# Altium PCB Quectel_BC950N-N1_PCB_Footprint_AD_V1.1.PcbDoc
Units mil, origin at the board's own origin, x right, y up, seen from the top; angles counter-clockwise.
Board outline 6000 x 4000 mil, 2 copper layers (Top Layer, Bottom Layer); 1 components, 0 nets, 94 pads, 0 vias.
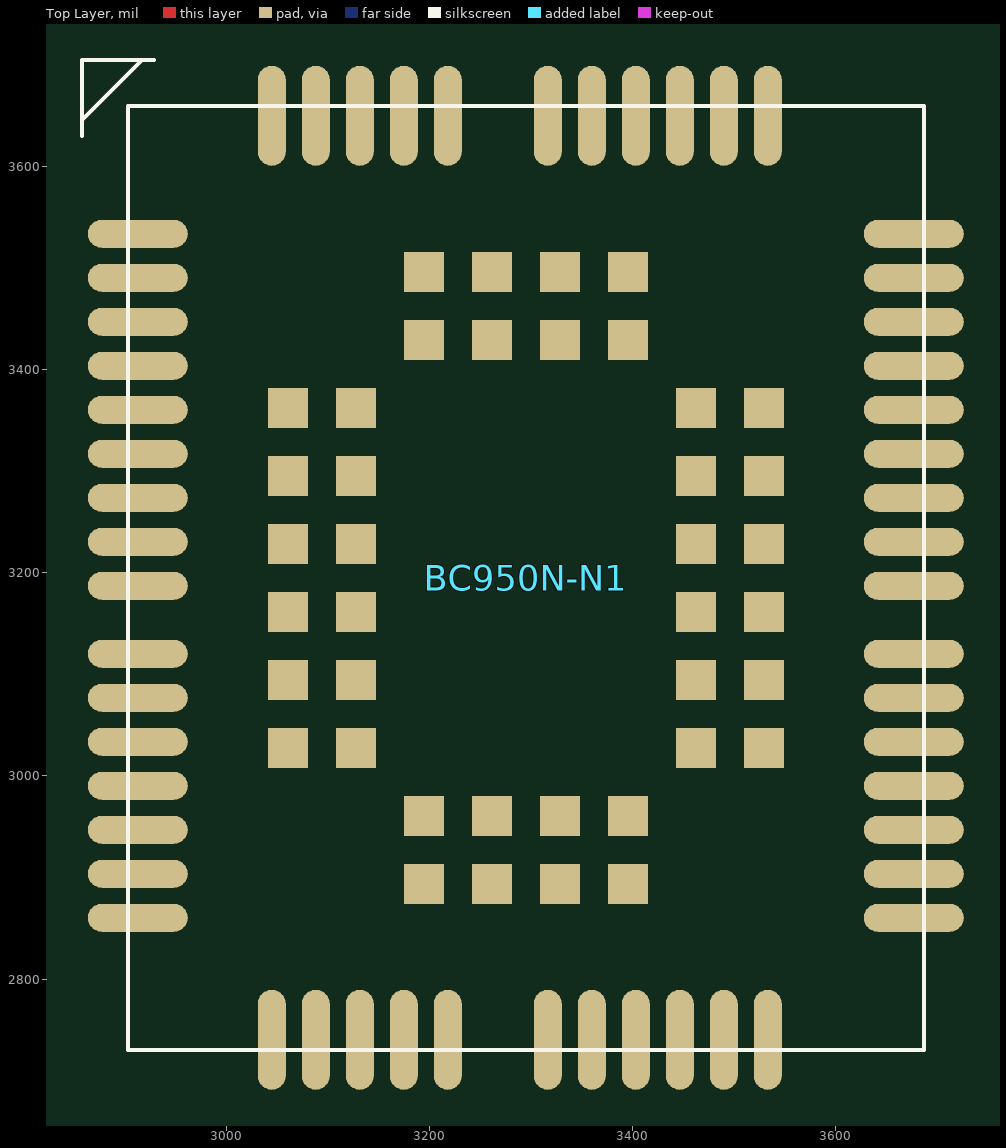
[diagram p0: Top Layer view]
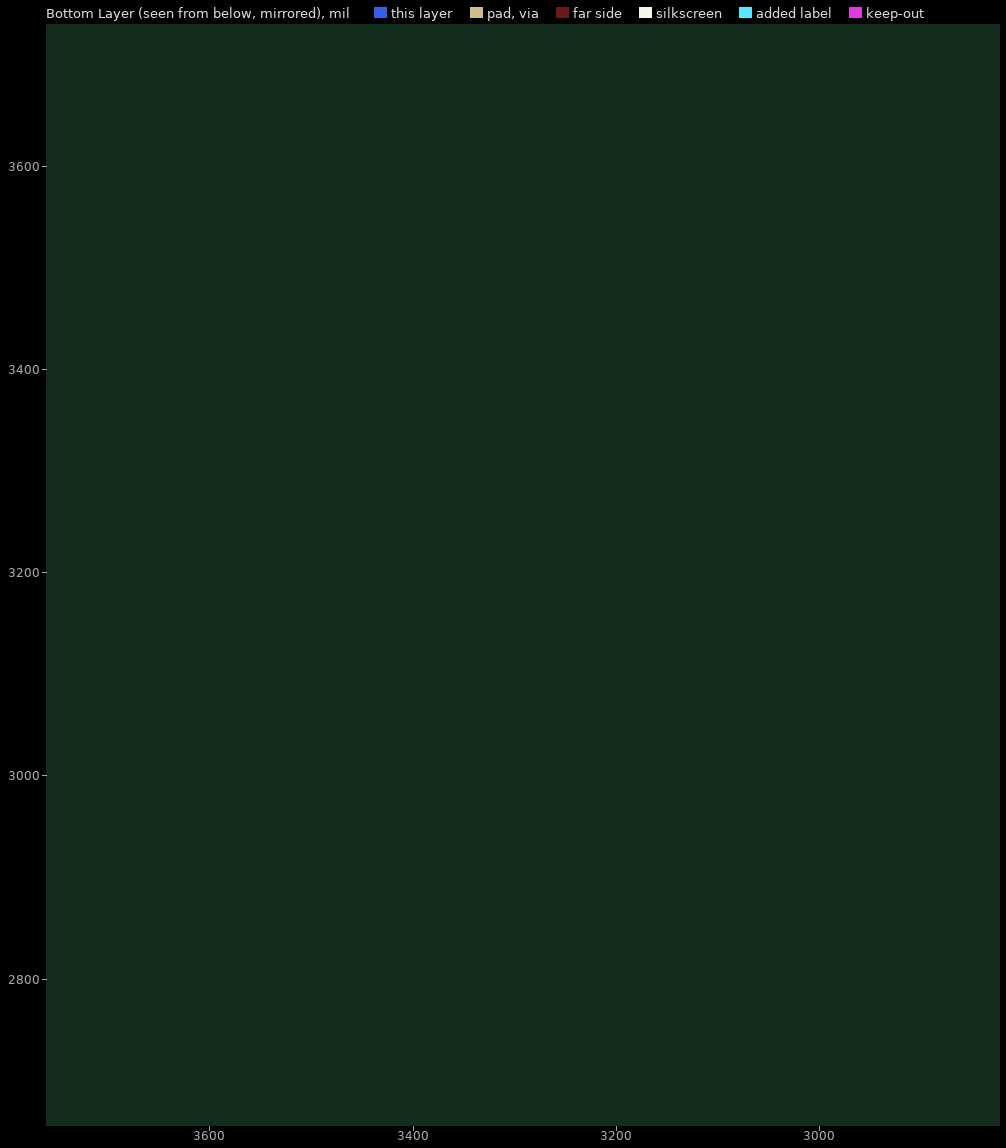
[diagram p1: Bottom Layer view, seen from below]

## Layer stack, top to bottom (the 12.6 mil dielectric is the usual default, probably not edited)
Top Layer: signal copper 1.4
Dielectric: dielectric 12.6, FR-4, Dk 4.8
Bottom Layer: signal copper 1.4

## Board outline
1000,1000 7000,1000 7000,5000 1000,5000

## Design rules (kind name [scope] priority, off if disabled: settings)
Clearance [All] p1: gap=10
PolygonConnect [All] p1: connectstyle=Relief reliefconductorwidth=10 reliefentries=4 polygonreliefangle="90 Angle" airgapwidth=10
RoutingVias [All] p1: holewidth=28 width=50 viastyle="Through Hole" minholewidth=28 minwidth=50 maxholewidth=28 maxwidth=50
SolderMaskExpansion [All] p1: expansion=4
Width [All] p1: maxlimit=10 minlimit=10 preferedwidth=10
28 further rules are at their usual default settings.

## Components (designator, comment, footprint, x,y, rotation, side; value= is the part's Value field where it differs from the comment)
BC950N-N1 "Comment" BC950N-N1 3295,3195 r0 top

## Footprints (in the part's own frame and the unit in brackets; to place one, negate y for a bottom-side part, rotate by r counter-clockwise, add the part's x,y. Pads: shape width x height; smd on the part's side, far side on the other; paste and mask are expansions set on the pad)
BC950N-N1 [mm]
  oval 2.5x0.7 smd mask+0.05: 1(-9.7,8.6) 2(-9.7,7.5) 3(-9.7,6.4) 4(-9.7,5.3) 5(-9.7,4.2) 6(-9.7,3.1) 7(-9.7,2) 8(-9.7,0.9) 9(-9.7,-0.2) 10(-9.7,-1.9) 11(-9.7,-3) 12(-9.7,-4.1) 13(-9.7,-5.2) 14(-9.7,-6.3) 15(-9.7,-7.4) 16(-9.7,-8.5) 28(9.7,-8.5) 29(9.7,-7.4) 30(9.7,-6.3) 31(9.7,-5.2) 32(9.7,-4.1) 33(9.7,-3) 34(9.7,-1.9) 35(9.7,-0.2) 36(9.7,0.9) 37(9.7,2) 38(9.7,3.1) 39(9.7,4.2) 40(9.7,5.3) 41(9.7,6.4) 42(9.7,7.5) 43(9.7,8.6)
  oval 0.7x2.5 smd mask+0.05: 17(-6.35,-11.55) 18(-5.25,-11.55) 19(-4.15,-11.55) 20(-3.05,-11.55) 21(-1.95,-11.55) 22(0.55,-11.55) 23(1.65,-11.55) 24(2.75,-11.55) 25(3.85,-11.55) 26(4.95,-11.55) 27(6.05,-11.55) 44(6.05,11.55) 45(4.95,11.55) 46(3.85,11.55) 47(2.75,11.55) 48(1.65,11.55) 49(0.55,11.55) 50(-1.95,11.55) 51(-3.05,11.55) 52(-4.15,11.55) 53(-5.25,11.55) 54(-6.35,11.55)
  rect 1x1 smd mask+0.05: 55(-5.95,4.25) 56(-5.95,2.55) 57(-5.95,0.85) 58(-5.95,-0.85) 59(-5.95,-2.55) 60(-5.95,-4.25) 61(-2.55,-7.65) 62(-0.85,-7.65) 63(0.85,-7.65) 64(2.55,-7.65) 65(5.95,-4.25) 66(5.95,-2.55) 67(5.95,-0.85) 68(5.95,0.85) 69(5.95,2.55) 70(5.95,4.25) 71(2.55,7.65) 72(0.85,7.65) 73(-0.85,7.65) 74(-2.55,7.65) 75(-4.25,4.25) 76(-4.25,2.55) 77(-4.25,0.85) 78(-4.25,-0.85) 79(-4.25,-2.55) 80(-4.25,-4.25) 81(-2.55,-5.95) 82(-0.85,-5.95) 83(0.85,-5.95) 84(2.55,-5.95) 85(4.25,-4.25) 86(4.25,-2.55) 87(4.25,-0.85) 88(4.25,0.85) 89(4.25,2.55) 90(4.25,4.25) 91(2.55,5.95) 92(0.85,5.95) 93(-0.85,5.95) 94(-2.55,5.95)
  silkscreen extent -11.1,-11.8 9.95,12.95

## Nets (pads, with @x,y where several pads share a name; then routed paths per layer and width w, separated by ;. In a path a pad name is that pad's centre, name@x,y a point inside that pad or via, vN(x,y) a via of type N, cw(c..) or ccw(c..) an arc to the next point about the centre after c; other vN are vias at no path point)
pads on no net: BC950N-N1.1 BC950N-N1.2 BC950N-N1.3 BC950N-N1.4 BC950N-N1.5 BC950N-N1.6 BC950N-N1.7 BC950N-N1.8 BC950N-N1.9 BC950N-N1.10 BC950N-N1.11 BC950N-N1.12 BC950N-N1.13 BC950N-N1.14 BC950N-N1.15 BC950N-N1.16 BC950N-N1.17 BC950N-N1.18 BC950N-N1.19 BC950N-N1.20 BC950N-N1.21 BC950N-N1.22 BC950N-N1.23 BC950N-N1.24 BC950N-N1.25 BC950N-N1.26 BC950N-N1.27 BC950N-N1.28 BC950N-N1.29 BC950N-N1.30 BC950N-N1.31 BC950N-N1.32 BC950N-N1.33 BC950N-N1.34 BC950N-N1.35 BC950N-N1.36 BC950N-N1.37 BC950N-N1.38 BC950N-N1.39 BC950N-N1.40 BC950N-N1.41 BC950N-N1.42 BC950N-N1.43 BC950N-N1.44 BC950N-N1.45 BC950N-N1.46 BC950N-N1.47 BC950N-N1.48 BC950N-N1.49 BC950N-N1.50 BC950N-N1.51 BC950N-N1.52 BC950N-N1.53 BC950N-N1.54 BC950N-N1.55 BC950N-N1.56 BC950N-N1.57 BC950N-N1.58 BC950N-N1.59 BC950N-N1.60 BC950N-N1.61 BC950N-N1.62 BC950N-N1.63 BC950N-N1.64 BC950N-N1.65 BC950N-N1.66 BC950N-N1.67 BC950N-N1.68 BC950N-N1.69 BC950N-N1.70 BC950N-N1.71 BC950N-N1.72 BC950N-N1.73 BC950N-N1.74 BC950N-N1.75 BC950N-N1.76 BC950N-N1.77 BC950N-N1.78 BC950N-N1.79 BC950N-N1.80 BC950N-N1.81 BC950N-N1.82 BC950N-N1.83 BC950N-N1.84 BC950N-N1.85 BC950N-N1.86 BC950N-N1.87 BC950N-N1.88 BC950N-N1.89 BC950N-N1.90 BC950N-N1.91 BC950N-N1.92 BC950N-N1.93 BC950N-N1.94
